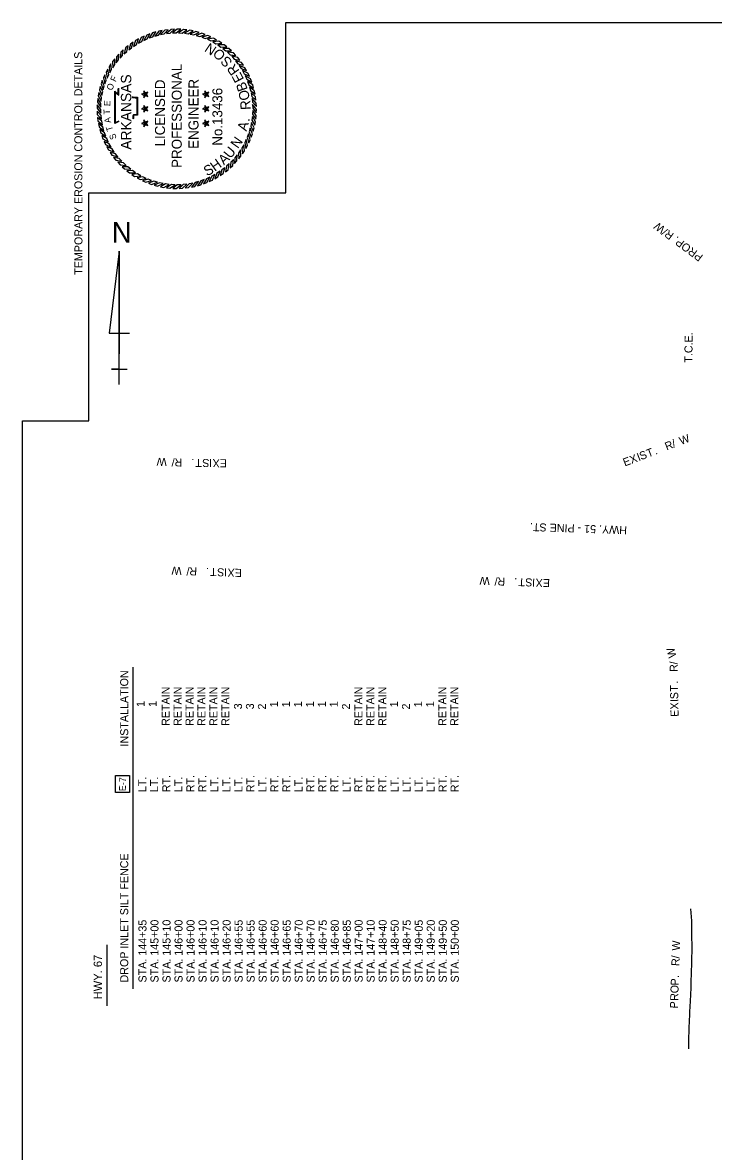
# Model space of a CAD drawing. Extents: x 991974 to 993016, y 1842702 to 1844298.
# Drawn here: x 991974 to 992491, y 1843452 to 1844298 of the extents above; entities that cross this region are included whole.
import ezdxf

# ---------------------------------------------------------------- set-up
doc = ezdxf.new("R2010")
doc.units = 0
for name, color, linetype in [('1', 7, 'Continuous'), ('44', 7, 'Continuous'), ('63', 7, 'Continuous'), ('Default', 7, 'Continuous'), ('G-ANNO-SYMB', 7, 'Continuous'), ('G-ANNO-TEXT', 7, 'Continuous'), ('R_Draft', 7, 'Continuous'), ('R_Proposed Const Limits', 7, 'Continuous')]:
    doc.layers.add(name, color=color, linetype=linetype)

msp = doc.modelspace()

# ---------------------------------------------------------------- linework, layer by layer
at = {"layer": '1'}
msp.add_lwpolyline([(992043.64, 1843720.75), (992043.64, 1843733.5), (992054.14, 1843733.5), (992054.14, 1843720.75)], close=True, dxfattribs=at)
at = {"layer": '44'}
for p, q in [((992056.89, 1843573.71), (992056.89, 1843814.71)), ((992037.3, 1843561.02), (992037.3, 1843606.6))]:
    msp.add_line(p, q, dxfattribs=at)
at = {"layer": '63'}
for p, q in [((992046.47, 1844126.56), (992038.77, 1844065.02)), ((992046.47, 1844026.56), (992046.47, 1844126.56)), ((992046.47, 1844126.56), (992046.47, 1844049.63)), ((992038.77, 1844065.02), (992054.16, 1844065.02)), ((992046.47, 1844026.56), (992046.47, 1844049.63)), ((992046.47, 1844038.1), (992040.7, 1844038.1)), ((992040.7, 1844038.1), (992052.23, 1844038.1)), ((992046.47, 1844026.56), (992046.47, 1844038.1))]:
    msp.add_line(p, q, dxfattribs=at)
at = {"layer": 'Default'}
msp.add_lwpolyline([(993016.34, 1842702.47), (991974.02, 1842702.47), (991974.02, 1843999.48), (992023.57, 1843999.48), (992023.57, 1844170.33), (992171.07, 1844170.33), (992171.07, 1844297.83), (993016.34, 1844297.83)], close=True, dxfattribs=at)
msp.add_lwpolyline([(993016.34, 1842702.47), (991974.02, 1842702.47), (991974.02, 1843999.48), (992023.57, 1843999.48), (992023.57, 1844170.33), (992171.07, 1844170.33), (992171.07, 1844297.83), (993016.34, 1844297.83)], close=True, dxfattribs=at)
msp.add_lwpolyline([(993016.34, 1842702.47), (991974.02, 1842702.47), (991974.02, 1843999.48), (992023.57, 1843999.48), (992023.57, 1844170.33), (992171.07, 1844170.33), (992171.07, 1844297.83), (993016.34, 1844297.83)], close=True, dxfattribs=at)
at = {"layer": 'G-ANNO-SYMB'}
for points in [[(992078.46, 1844291.84), (992075.95, 1844291.31), (992073.11, 1844287.73), (992075.78, 1844288.46)], [(992083.1, 1844292.52), (992080.55, 1844292.19), (992077.43, 1844288.85), (992080.16, 1844289.37)], [(992087.77, 1844292.84), (992085.21, 1844292.71), (992081.84, 1844289.62), (992084.59, 1844289.93)], [(992092.46, 1844292.79), (992089.89, 1844292.86), (992086.29, 1844290.05), (992089.06, 1844290.13)], [(992097.12, 1844292.37), (992094.57, 1844292.64), (992090.76, 1844290.12), (992093.53, 1844289.99)], [(992101.74, 1844291.59), (992099.22, 1844292.06), (992095.22, 1844289.84), (992097.97, 1844289.5)], [(992056.86, 1844283.16), (992054.75, 1844281.71), (992053.49, 1844277.32), (992055.68, 1844279.01)], [(992060.88, 1844285.56), (992058.66, 1844284.29), (992057.06, 1844280), (992059.37, 1844281.53)], [(992065.08, 1844287.65), (992062.76, 1844286.55), (992060.83, 1844282.4), (992063.26, 1844283.74)], [(992069.43, 1844289.39), (992067.03, 1844288.48), (992064.78, 1844284.5), (992067.3, 1844285.64)], [(992073.9, 1844290.79), (992071.44, 1844290.07), (992068.88, 1844286.28), (992071.49, 1844287.22)], [(992106.28, 1844290.45), (992103.81, 1844291.12), (992099.65, 1844289.22), (992102.36, 1844288.66)], [(992110.72, 1844288.95), (992108.31, 1844289.81), (992104.01, 1844288.25), (992106.67, 1844287.48)], [(992115.03, 1844287.11), (992112.69, 1844288.16), (992108.28, 1844286.94), (992110.88, 1844285.96)], [(992119.18, 1844284.94), (992116.93, 1844286.17), (992112.44, 1844285.3), (992114.95, 1844284.12)], [(992123.15, 1844282.45), (992121, 1844283.85), (992116.46, 1844283.34), (992118.87, 1844281.96)], [(992049.45, 1844277.44), (992047.59, 1844275.68), (992047.03, 1844271.14), (992048.92, 1844273.16)], [(992053.04, 1844280.45), (992051.05, 1844278.84), (992050.14, 1844274.36), (992052.18, 1844276.22)], [(992126.91, 1844279.66), (992124.88, 1844281.22), (992120.31, 1844281.06), (992122.6, 1844279.51)], [(992130.44, 1844276.58), (992128.54, 1844278.3), (992123.97, 1844278.5), (992126.13, 1844276.77)], [(992133.72, 1844273.23), (992131.95, 1844275.09), (992127.42, 1844275.65), (992129.44, 1844273.75)], [(992040.23, 1844266.88), (992038.83, 1844264.73), (992039.34, 1844260.18), (992040.72, 1844262.59)], [(992043.02, 1844270.64), (992041.46, 1844268.6), (992041.62, 1844264.03), (992043.17, 1844266.33)], [(992046.1, 1844274.17), (992044.38, 1844272.26), (992044.18, 1844267.69), (992045.91, 1844269.86)], [(992136.72, 1844269.64), (992135.11, 1844271.63), (992130.63, 1844272.54), (992132.5, 1844270.49)], [(992139.43, 1844265.82), (992137.98, 1844267.93), (992133.59, 1844269.19), (992135.29, 1844267)], [(992035.57, 1844258.76), (992034.52, 1844256.42), (992035.74, 1844252.01), (992036.72, 1844254.6)], [(992037.74, 1844262.91), (992036.51, 1844260.66), (992037.38, 1844256.17), (992038.56, 1844258.68)], [(992141.84, 1844261.8), (992140.56, 1844264.02), (992136.28, 1844265.62), (992137.8, 1844263.31)], [(992143.92, 1844257.6), (992142.82, 1844259.92), (992138.68, 1844261.85), (992140.01, 1844259.42)], [(992145.67, 1844253.25), (992144.75, 1844255.65), (992140.77, 1844257.9), (992141.91, 1844255.38)], [(992032.23, 1844250.01), (992031.56, 1844247.53), (992033.46, 1844243.37), (992034.02, 1844246.09)], [(992033.73, 1844254.45), (992032.87, 1844252.03), (992034.43, 1844247.74), (992035.2, 1844250.4)], [(992147.07, 1844248.78), (992146.34, 1844251.24), (992142.55, 1844253.8), (992143.49, 1844251.19)], [(992148.11, 1844244.22), (992147.58, 1844246.73), (992144, 1844249.57), (992144.74, 1844246.9)], [(992030.31, 1844240.85), (992030.03, 1844238.3), (992032.56, 1844234.48), (992032.69, 1844237.25)], [(992031.09, 1844245.47), (992030.62, 1844242.95), (992032.83, 1844238.95), (992033.18, 1844241.7)], [(992065.72, 1844244.11), (992064.88, 1844244.72), (992062.99, 1844244.11), (992064.88, 1844243.5)], [(992065.72, 1844244.11), (992066.04, 1844245.1), (992064.88, 1844246.71), (992064.88, 1844244.72)], [(992065.72, 1844244.11), (992064.88, 1844243.5), (992064.88, 1844241.52), (992066.04, 1844243.12)], [(992065.72, 1844244.11), (992066.76, 1844244.11), (992067.93, 1844245.72), (992066.04, 1844245.1)], [(992065.72, 1844244.11), (992066.04, 1844243.12), (992067.93, 1844242.51), (992066.76, 1844244.11)], [(992111.4, 1844244.11), (992110.56, 1844244.72), (992108.67, 1844244.11), (992110.56, 1844243.5)], [(992111.4, 1844244.11), (992111.72, 1844245.1), (992110.56, 1844246.71), (992110.56, 1844244.72)], [(992111.4, 1844244.11), (992110.56, 1844243.5), (992110.56, 1844241.52), (992111.72, 1844243.12)], [(992111.4, 1844244.11), (992112.44, 1844244.11), (992113.61, 1844245.72), (992111.72, 1844245.1)], [(992111.4, 1844244.11), (992111.72, 1844243.12), (992113.61, 1844242.51), (992112.44, 1844244.11)], [(992148.79, 1844239.58), (992148.46, 1844242.13), (992145.12, 1844245.24), (992145.64, 1844242.52)], [(992149.11, 1844234.91), (992148.98, 1844237.47), (992145.89, 1844240.84), (992146.2, 1844238.09)], [(992029.89, 1844236.18), (992029.82, 1844233.62), (992032.63, 1844230.01), (992032.55, 1844232.78)], [(992065.72, 1844233.2), (992064.88, 1844233.82), (992062.99, 1844233.2), (992064.88, 1844232.59)], [(992065.72, 1844233.2), (992066.04, 1844234.19), (992064.88, 1844235.8), (992064.88, 1844233.82)], [(992065.72, 1844233.2), (992064.88, 1844232.59), (992064.88, 1844230.61), (992066.04, 1844232.21)], [(992065.72, 1844233.2), (992066.76, 1844233.2), (992067.93, 1844234.81), (992066.04, 1844234.19)], [(992065.72, 1844233.2), (992066.04, 1844232.21), (992067.93, 1844231.6), (992066.76, 1844233.2)], [(992111.4, 1844233.2), (992110.56, 1844233.82), (992108.67, 1844233.2), (992110.56, 1844232.59)], [(992111.4, 1844233.2), (992111.72, 1844234.19), (992110.56, 1844235.8), (992110.56, 1844233.82)], [(992111.4, 1844233.2), (992110.56, 1844232.59), (992110.56, 1844230.61), (992111.72, 1844232.21)], [(992111.4, 1844233.2), (992112.44, 1844233.2), (992113.61, 1844234.81), (992111.72, 1844234.19)], [(992111.4, 1844233.2), (992111.72, 1844232.21), (992113.61, 1844231.6), (992112.44, 1844233.2)], [(992149.06, 1844230.22), (992149.13, 1844232.79), (992146.32, 1844236.39), (992146.41, 1844233.62)], [(992029.84, 1844231.5), (992029.97, 1844228.94), (992033.06, 1844225.56), (992032.75, 1844228.32)], [(992030.16, 1844226.82), (992030.49, 1844224.28), (992033.83, 1844221.16), (992033.31, 1844223.88)], [(992065.72, 1844222.29), (992066.04, 1844223.28), (992064.88, 1844224.89), (992064.88, 1844222.91)], [(992065.72, 1844222.29), (992066.76, 1844222.29), (992067.93, 1844223.9), (992066.04, 1844223.28)], [(992111.4, 1844222.29), (992111.72, 1844223.28), (992110.56, 1844224.89), (992110.56, 1844222.91)], [(992111.4, 1844222.29), (992112.44, 1844222.29), (992113.61, 1844223.9), (992111.72, 1844223.28)], [(992147.86, 1844220.94), (992148.34, 1844223.46), (992146.12, 1844227.46), (992145.77, 1844224.71)], [(992148.64, 1844225.56), (992148.92, 1844228.11), (992146.39, 1844231.92), (992146.26, 1844229.15)], [(992030.84, 1844222.19), (992031.37, 1844219.68), (992034.95, 1844216.83), (992034.22, 1844219.51)], [(992031.89, 1844217.62), (992032.61, 1844215.16), (992036.4, 1844212.6), (992035.46, 1844215.21)], [(992065.72, 1844222.29), (992064.88, 1844222.91), (992062.99, 1844222.29), (992064.88, 1844221.68)], [(992065.72, 1844222.29), (992064.88, 1844221.68), (992064.88, 1844219.7), (992066.04, 1844221.3)], [(992065.72, 1844222.29), (992066.04, 1844221.3), (992067.93, 1844220.69), (992066.76, 1844222.29)], [(992111.4, 1844222.29), (992110.56, 1844222.91), (992108.67, 1844222.29), (992110.56, 1844221.68)], [(992111.4, 1844222.29), (992110.56, 1844221.68), (992110.56, 1844219.7), (992111.72, 1844221.3)], [(992111.4, 1844222.29), (992111.72, 1844221.3), (992113.61, 1844220.69), (992112.44, 1844222.29)], [(992145.22, 1844211.96), (992146.09, 1844214.37), (992144.52, 1844218.67), (992143.75, 1844216.01)], [(992146.72, 1844216.4), (992147.39, 1844218.87), (992145.49, 1844223.03), (992144.93, 1844220.32)], [(992033.29, 1844213.15), (992034.2, 1844210.76), (992038.18, 1844208.5), (992037.04, 1844211.03)], [(992035.03, 1844208.81), (992036.13, 1844206.49), (992040.28, 1844204.56), (992038.94, 1844206.98)], [(992141.21, 1844203.5), (992142.44, 1844205.75), (992141.57, 1844210.24), (992140.39, 1844207.73)], [(992143.39, 1844207.65), (992144.43, 1844209.99), (992143.21, 1844214.4), (992142.23, 1844211.8)], [(992037.12, 1844204.61), (992038.39, 1844202.39), (992042.68, 1844200.78), (992041.15, 1844203.1)], [(992039.52, 1844200.59), (992040.97, 1844198.47), (992045.36, 1844197.21), (992043.66, 1844199.4)], [(992132.85, 1844192.24), (992134.57, 1844194.14), (992134.77, 1844198.71), (992133.04, 1844196.55)], [(992135.93, 1844195.77), (992137.5, 1844197.8), (992137.34, 1844202.37), (992135.78, 1844200.08)], [(992138.72, 1844199.53), (992140.13, 1844201.68), (992139.61, 1844206.22), (992138.24, 1844203.81)], [(992042.23, 1844196.77), (992043.84, 1844194.77), (992048.32, 1844193.86), (992046.46, 1844195.91)], [(992045.24, 1844193.18), (992047, 1844191.31), (992051.54, 1844190.75), (992049.52, 1844192.65)], [(992125.91, 1844185.96), (992127.91, 1844187.57), (992128.82, 1844192.05), (992126.77, 1844190.18)], [(992129.5, 1844188.96), (992131.37, 1844190.73), (992131.93, 1844195.26), (992130.03, 1844193.24)], [(992048.51, 1844189.83), (992050.42, 1844188.11), (992054.98, 1844187.91), (992052.82, 1844189.64)], [(992052.04, 1844186.75), (992054.08, 1844185.18), (992058.64, 1844185.34), (992056.35, 1844186.9)], [(992055.8, 1844183.95), (992057.95, 1844182.55), (992062.5, 1844183.07), (992060.09, 1844184.44)], [(992059.77, 1844181.46), (992062.02, 1844180.24), (992066.51, 1844181.11), (992064, 1844182.29)], [(992109.53, 1844177.01), (992111.92, 1844177.93), (992114.18, 1844181.91), (992111.65, 1844180.77)], [(992113.87, 1844178.76), (992116.19, 1844179.86), (992118.12, 1844184), (992115.7, 1844182.67)], [(992118.07, 1844180.84), (992120.29, 1844182.12), (992121.9, 1844186.4), (992119.58, 1844184.88)], [(992122.09, 1844183.25), (992124.21, 1844184.69), (992125.47, 1844189.09), (992123.28, 1844187.39)], [(992063.92, 1844179.29), (992066.26, 1844178.24), (992070.67, 1844179.47), (992068.08, 1844180.45)], [(992068.23, 1844177.45), (992070.65, 1844176.59), (992074.94, 1844178.16), (992072.28, 1844178.93)], [(992072.67, 1844175.96), (992075.15, 1844175.29), (992079.31, 1844177.19), (992076.59, 1844177.75)], [(992077.21, 1844174.82), (992079.73, 1844174.34), (992083.73, 1844176.56), (992080.98, 1844176.91)], [(992081.83, 1844174.04), (992084.38, 1844173.76), (992088.2, 1844176.29), (992085.43, 1844176.42)], [(992086.5, 1844173.62), (992089.06, 1844173.54), (992092.67, 1844176.36), (992089.89, 1844176.27)], [(992091.18, 1844173.57), (992093.74, 1844173.7), (992097.12, 1844176.79), (992094.36, 1844176.48)], [(992095.86, 1844173.89), (992098.4, 1844174.21), (992101.52, 1844177.56), (992098.8, 1844177.04)], [(992100.49, 1844174.57), (992103, 1844175.1), (992105.85, 1844178.68), (992103.17, 1844177.94)], [(992105.06, 1844175.61), (992107.52, 1844176.34), (992110.07, 1844180.13), (992107.47, 1844179.19)]]:
    msp.add_lwpolyline(points, close=True, dxfattribs=at)
for points in [[(992046.18, 1844223.65), (992043.16, 1844222.25), (992043.15, 1844246.32), (992045.68, 1844244.31), (992045.66, 1844245.94), (992045.64, 1844247.31), (992045.79, 1844248.67)], [(992046.02, 1844223.99), (992043.55, 1844222.85), (992043.53, 1844245.53), (992046.07, 1844243.51), (992046.04, 1844245.95), (992046.02, 1844247.29), (992046.17, 1844248.63)], [(992055.97, 1844242.29), (992056.38, 1844241.78), (992057.02, 1844241.6), (992058.32, 1844241.46), (992059.62, 1844241.46), (992059.62, 1844228.79), (992057.76, 1844228.79), (992056.98, 1844228.79), (992056.71, 1844227.92), (992056.71, 1844226.16), (992056.37, 1844225.93)], [(992056.26, 1844242.53), (992056.59, 1844242.12), (992057.09, 1844241.98), (992058.34, 1844241.84), (992060, 1844241.84), (992060, 1844228.41), (992057.76, 1844228.41), (992057.26, 1844228.41), (992057.09, 1844227.87), (992057.09, 1844225.95), (992056.58, 1844225.62)]]:
    msp.add_lwpolyline(points, dxfattribs=at)
at = {"layer": 'R_Proposed Const Limits'}
msp.add_lwpolyline([(992472.9, 1843528.84), (992473.1, 1843534.6), (992473.28, 1843544.6), (992473.65, 1843554.59), (992473.75, 1843556.6), (992474.16, 1843564.58), (992474.67, 1843574.57), (992474.86, 1843580.08), (992475.02, 1843584.56), (992475.37, 1843594.56), (992475.48, 1843604.56), (992475.35, 1843614.57), (992475.29, 1843624.58), (992474.53, 1843633.79)], dxfattribs=at)

# ---------------------------------------------------------------- texts
at = {"layer": '1'}
msp.add_text('E-7 ', height=4.999, rotation=89.61324, dxfattribs=at).set_placement((992051.33, 1843721.91))
at = {"layer": '44'}
for s, height, p in [('INSTALLATION', 6, (992053.14, 1843755.35)), ('RT.', 6, (992084.66, 1843721.07)), ('RT.', 6, (992102.66, 1843721.07)), ('RT.', 6, (992111.66, 1843721.07)), ('RT.', 6, (992147.66, 1843721.07)), ('RT.', 6, (992165.66, 1843721.07)), ('RT.', 6, (992174.66, 1843721.07)), ('RT.', 6, (992192.61, 1843721.07)), ('RT.', 6, (992201.56, 1843721.07)), ('RT.', 6, (992210.56, 1843721.07)), ('RT.', 6, (992228.56, 1843721.07)), ('RT.', 6, (992237.56, 1843721.07)), ('RT.', 6, (992246.56, 1843721.07)), ('RT.', 6, (992291.56, 1843721.07)), ('RT.', 6, (992300.56, 1843721.07)), ('LT.', 6, (992066.61, 1843721.21)), ('LT.', 6, (992075.56, 1843721.21)), ('LT.', 6, (992093.66, 1843721.21)), ('LT.', 6, (992120.66, 1843721.21)), ('LT.', 6, (992129.66, 1843721.21)), ('LT.', 6, (992138.66, 1843721.21)), ('LT.', 6, (992156.66, 1843721.07)), ('LT.', 6, (992183.66, 1843721.07)), ('LT.', 6, (992219.66, 1843721.07)), ('LT.', 6, (992255.61, 1843721.07)), ('LT.', 6, (992264.61, 1843721.07)), ('LT.', 6, (992273.61, 1843721.07)), ('LT.', 6, (992282.61, 1843721.07)), ('DROP INLET SILT FENCE', 6, (992053.14, 1843578.5)), ('HWY. 67', 6.25, (992033.52, 1843565.87))]:
    msp.add_text(s, height=height, rotation=90, dxfattribs=at).set_placement(p)
at = {"layer": '63'}
msp.add_text('N', height=15.38, rotation=0, dxfattribs=at).set_placement((992040.83, 1844132.97))
at = {"layer": 'G-ANNO-SYMB'}
for s, height, rotation, p in [('N', 7.5, 146.10067, (992119.91, 1844278.94)), ('O', 7.5, 134.77573, (992126.66, 1844273.73)), ('PROFESSIONAL', 7.5, 90, (992093.23, 1844188.92)), ('S', 7.5, 133.48784, (992131.64, 1844268.58)), ('R', 7.5, 125.65967, (992136.74, 1844261.69)), ('F', 4.75, 65.36282, (992043.71, 1844253.04)), ('ARKANSAS', 7.747, 90, (992055.4, 1844202.58)), ('E', 7.5, 117.83149, (992140.06, 1844255.35)), ('O', 4.75, 71.2218, (992041.21, 1844246.64)), ('LICENSED', 7.5, 90, (992080.68, 1844204.99)), ('ENGINEER', 7.5, 90, (992105.77, 1844203.2)), ('B', 7.5, 108.88501, (992142.77, 1844247.77)), ('No.13436', 7.47, 90, (992123.65, 1844205.57)), ('O', 7.5, 101.42961, (992144.36, 1844240.25)), ('T', 4.75, 91.47887, (992039.44, 1844229.04)), ('E', 4.75, 86.67203, (992039.58, 1844235.12)), ('R', 7.5, 93.22866, (992144.84, 1844232.58)), ('A', 4.75, 98.67877, (992040.38, 1844222.91)), ('.', 7.5, 81.30002, (992143.89, 1844223.38)), ('T', 4.75, 106.90148, (992041.89, 1844217.15)), ('A', 7.5, 73.09908, (992141.71, 1844216.01)), ('S', 4.75, 109.77256, (992044.6, 1844211.11)), ('N', 7.5, 54.93262, (992135.27, 1844202.94)), ('A', 7.5, 43.44722, (992124.8, 1844190.71)), ('U', 7.5, 50.90262, (992129.69, 1844195.38)), ('S', 7.5, 28.16364, (992112.07, 1844182.52)), ('H', 7.5, 35.61905, (992117.95, 1844185.94))]:
    msp.add_text(s, height=height, rotation=rotation, dxfattribs=at).set_placement(p)
at = {"layer": 'G-ANNO-TEXT'}
msp.add_text('TEMPORARY EROSION CONTROL DETAILS', height=6, rotation=90.07909, dxfattribs=at).set_placement((992018.89, 1844108.85))
at = {"layer": 'R_Draft'}
for s, rotation, p in [('PROP. R/W', 143.53223, (992484.16, 1844123.22)), ('T.C.E.', 89.40901, (992475.66, 1844042.97)), ('W', 20.9463, (992467.19, 1843981.28)), ('T', 20.9463, (992442.61, 1843971.88)), ('R', 20.9463, (992456.42, 1843977.16)), ('/', 20.9463, (992461.71, 1843979.19)), ('W', 178.24464, (992082.11, 1843971.49)), ('/', 178.24464, (992087.97, 1843971.31)), ('R', 178.24464, (992093.64, 1843971.13)), ('.', 178.24464, (992102.56, 1843970.86)), ('T', 179.30223, (992108.31, 1843970.81)), ('S', 179.30223, (992113.98, 1843970.74)), ('I', 179.30223, (992115.96, 1843970.72)), ('X', 179.30223, (992121.72, 1843970.65)), ('E', 179.30223, (992127.11, 1843970.58)), ('E', 20.9463, (992425.05, 1843965.15)), ('X', 20.9463, (992430.08, 1843967.08)), ('I', 20.9463, (992435.46, 1843969.14)), ('S', 20.9463, (992437.32, 1843969.85)), ('.', 20.9463, (992448.08, 1843973.97)), ('HWY. 51 - PINE ST.', 178.05575, (992426.79, 1843920.37)), ('W', 178.15992, (992093.27, 1843889.83)), ('/', 178.15992, (992099.12, 1843889.65)), ('R', 178.15992, (992104.79, 1843889.46)), ('.', 178.15992, (992113.71, 1843889.18)), ('T', 178.15992, (992119.57, 1843888.99)), ('S', 178.15992, (992125.24, 1843888.81)), ('I', 178.15992, (992127.22, 1843888.74)), ('X', 178.15992, (992132.98, 1843888.56)), ('E', 178.15992, (992138.36, 1843888.38)), ('W', 178.05575, (992324, 1843882.29)), ('/', 178.05575, (992329.86, 1843882.1)), ('R', 178.05575, (992335.52, 1843881.9)), ('.', 178.05575, (992344.45, 1843881.6)), ('T', 178.05575, (992350.3, 1843881.4)), ('S', 178.05575, (992355.97, 1843881.21)), ('I', 178.05575, (992357.95, 1843881.14)), ('X', 178.05575, (992363.71, 1843880.95)), ('E', 178.05575, (992369.1, 1843880.76)), ('W', 104.91415, (992463.85, 1843822.71)), ('/', 91.02618, (992464.63, 1843816.94)), ('R', 91.02618, (992464.73, 1843811.28)), ('T', 91.02618, (992465, 1843796.49)), ('.', 91.02618, (992464.89, 1843802.35)), ('RETAIN', 89.99998, (992084.16, 1843770.79)), ('RETAIN', 89.99998, (992093.11, 1843770.79)), ('RETAIN', 89.99998, (992102.05, 1843770.79)), ('RETAIN', 89.99998, (992111, 1843770.79)), ('RETAIN', 89.99998, (992119.95, 1843770.79)), ('RETAIN', 89.99998, (992128.9, 1843770.79)), ('RETAIN', 89.99998, (992228.56, 1843770.79)), ('RETAIN', 89.99998, (992237.51, 1843770.79)), ('RETAIN', 89.99998, (992246.46, 1843770.79)), ('RETAIN', 89.99998, (992291.4, 1843770.79)), ('RETAIN', 89.99998, (992300.35, 1843770.79)), ('S', 91.02618, (992465.1, 1843790.82)), ('1', 89.99998, (992065.44, 1843785.03)), ('1', 89.99998, (992074.39, 1843785.03)), ('3', 89.99998, (992138.34, 1843783.2)), ('3', 89.99998, (992147.29, 1843783.2)), ('2', 89.99998, (992156.29, 1843783.06)), ('1', 89.99998, (992165.29, 1843784.76)), ('1', 89.99998, (992174.29, 1843784.76)), ('1', 89.99998, (992183.24, 1843784.76)), ('1', 89.99998, (992192.19, 1843784.76)), ('1', 89.99998, (992201.14, 1843784.76)), ('1', 89.99998, (992210.09, 1843784.76)), ('2', 89.99998, (992219.24, 1843783.06)), ('1', 89.99998, (992255.19, 1843784.76)), ('2', 89.99998, (992264.19, 1843783.06)), ('1', 89.99998, (992273.19, 1843784.76)), ('1', 89.99998, (992282.19, 1843784.76)), ('I', 91.02618, (992465.14, 1843788.84)), ('X', 91.02618, (992465.24, 1843783.08)), ('E', 91.02618, (992465.34, 1843777.69)), ('STA. 144+35', 90, (992066.81, 1843578.5)), ('STA. 145+00', 90, (992075.81, 1843578.5)), ('STA. 145+10', 90, (992084.81, 1843578.5)), ('STA. 146+00', 90, (992093.81, 1843578.5)), ('STA. 146+00', 90, (992102.81, 1843578.5)), ('STA. 146+10', 90, (992111.81, 1843578.5)), ('STA. 146+10', 90, (992120.81, 1843578.5)), ('STA. 146+20', 90, (992129.81, 1843578.5)), ('STA. 146+55', 90, (992138.81, 1843578.5)), ('STA. 146+55', 90, (992147.81, 1843578.5)), ('STA. 146+60', 90, (992156.81, 1843578.5)), ('STA. 146+60', 90, (992165.81, 1843578.5)), ('STA. 146+65', 90, (992174.81, 1843578.5)), ('STA. 146+70', 90, (992183.81, 1843578.5)), ('STA. 146+70', 90, (992192.81, 1843578.5)), ('STA. 146+75', 90, (992201.81, 1843578.5)), ('STA. 146+80', 90, (992210.81, 1843578.5)), ('STA. 146+85', 90, (992219.81, 1843578.5)), ('STA. 147+00', 90, (992228.71, 1843578.5)), ('STA. 147+10', 90, (992237.71, 1843578.5)), ('STA. 148+40', 90, (992246.71, 1843578.5)), ('STA. 148+50', 90, (992255.71, 1843578.5)), ('STA. 148+75', 90, (992264.71, 1843578.5)), ('STA. 149+05', 90, (992273.71, 1843578.5)), ('STA. 149+20', 90, (992282.71, 1843578.5)), ('STA. 149+50', 90, (992291.71, 1843578.5)), ('STA. 150+00', 90, (992300.71, 1843578.5)), ('W', 88.03611, (992466.3, 1843602.26)), ('/', 88.03611, (992466.09, 1843596.41)), ('R', 88.03611, (992465.9, 1843590.74)), ('P', 88.03611, (992465.4, 1843576.15)), ('.', 88.03611, (992465.59, 1843581.82)), ('O', 88.03611, (992465.2, 1843570.3)), ('P', 88.03611, (992464.81, 1843558.97)), ('R', 88.03611, (992465.01, 1843564.63))]:
    msp.add_text(s, height=6, rotation=rotation, dxfattribs=at).set_placement(p)

doc.saveas('drawing.dxf')
